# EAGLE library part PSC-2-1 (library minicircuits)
Power Splitter / Combiner 2 Way-0° Source: minicircuits.com .. PSC-2-1.pdf
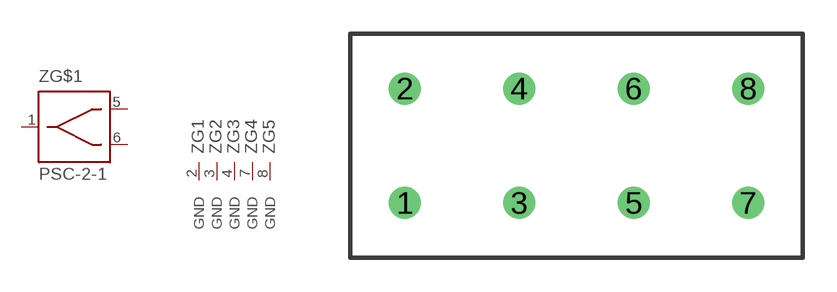
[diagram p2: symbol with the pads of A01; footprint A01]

Designator prefix Z; gates G$1=POWER-SPLITTER G1=GROUND G2=GROUND G3=GROUND G4=GROUND G5=GROUND

## PSC-2-1 (OC_FARNELL: unknown; OC_NEWARK: unknown)  [A01]
1  G$1:IN  in
2  G1:GND  pwr
3  G2:GND  pwr
4  G3:GND  pwr
5  G$1:OUT1  in
6  G$1:OUT2  in
7  G4:GND  pwr
8  G5:GND  pwr

## Footprint A01 (pad centres in mm)
CASE STYLE A01 Source: minicircuits.com .. PBP-10.7+.pdf
drill 0.9 pad 1.422 round: 1 -7.62,-2.54; 2 -7.62,2.54; 3 -2.54,-2.54; 4 -2.54,2.54; 5 2.54,-2.54; 6 2.54,2.54; 7 7.62,-2.54; 8 7.62,2.54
